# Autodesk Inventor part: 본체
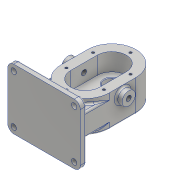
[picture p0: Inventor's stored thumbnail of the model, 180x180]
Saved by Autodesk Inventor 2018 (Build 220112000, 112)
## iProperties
Created: 2020-09
Part Number: 본체
Material: 알루미늄 6061
Document SubType Name: Modeling
Designer: Administrator
Density: 2.7 g/cm^3
Appearance: 알루미늄 - 평지
Mass: 1440.46 g
Surface Area: 785.636 cm^2
Volume: 533.505 cm^3
Author: Administrator
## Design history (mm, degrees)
sketch "스케치2"
  geometry: L1 (0, -22)-(0, 22); L2 (40, -22)-(40, 22); L3 (-40, 22)-(-40, -22); A1 r 40 centre (0, -22) between (-40, -22) and (40, -22); A2 r 40 centre (0, 22) between (40, 22) and (-40, 22); 1 further point
  constraints: 8 end point, 4 point on circle, 4 tangent, 2 centre point, 1 midpoint, 1 parallel, 1 vertical
  dimensions: "d8" = 40 radius of A2; "d9" = 44 distance of L2.start L2.end
extrude "돌출1" new body sketch "스케치2" distance "d11" = 53; taper "d12" = 0 deg
sketch "스케치3"
  geometry: C1 r 19 at (0, 22); A1 r 40 centre (0, 22) between (40, 22) and (-40, 22) reference; 1 further point
  constraints: 1 centre point, 1 coincident
  dimensions: "d13" = 38 diameter of C1
extrude "돌출2" join sketch "스케치3" distance "d14" = 17; taper "d15" = 0 deg
node "작업 평면1"
sketch "스케치4"
  geometry: L1 (40, 53)-(-40, 53) reference; L2 (-60, 83)-(-60, -17); L3 (60, 83)-(60, -17); L4 (-19, -17)-(19, -17) reference; L5 (0, -17)-(0, 83); L6 (60, -17)-(-60, -17); L7 (60, 83)-(-60, 83); 1 further point
  constraints: 10 end point, 2 parallel, 1 horizontal, 1 midpoint, 1 perpendicular, 1 vertical
  dimensions: "d19" = 100 distance of L5.start L5.end; "d89" = 120 distance of L3.end L2.end; "d90" = 30 distance between parallel lines of L1 L7; "d91" = 70 distance between parallel lines of L1 L6; "d92" = 60 distance between parallel lines of L3 L5
extrude "돌출3" join sketch "스케치4" distance "d20" = 10; taper "d21" = 0 deg
sketch "스케치5"
  geometry: L1 (60, 17)-(-60, 17) reference; L2 (0, -8)-(0, -45); L3 (40, -45)-(40, -8); L4 (-40, -45)-(-40, -8); L5 (-40, -45)-(40, -45); L6 (-40, -8)-(40, -8); 1 further point
  constraints: 10 end point, 2 horizontal, 1 vertical
  dimensions: "d23" = 37 distance of L2.start L2.end; "d26" = 40 distance between parallel lines of L2 L3; "d27" = 40 distance between parallel lines of L2 L4; "d93" = 25 distance between parallel lines of L1 L6; "d94" = 62 distance between parallel lines of L1 L5; "d95" = 20 distance from line of L1.start L3; "d96" = 25 distance from line of L2.start L1
extrude "돌출4" join sketch "스케치5" stored distance "d28" = 10; taper "d29" = 0 deg
sketch "스케치6"
  geometry: L1 (22, 53)-(-22, 53) reference; L2 (0, 53)-(0, 39); C1 r 11 at (0, 39); 1 further point
  constraints: 2 end point, 1 centre point, 1 coincident, 1 midpoint, 1 vertical
  dimensions: "d30" = 14 distance of L2.start L2.end; "d31" = 22 diameter of C1
extrude "돌출5" join sketch "스케치6" stored distance "d32" = 100; taper "d33" = 0 deg
sketch "스케치7"
  geometry: L1 (-24, 22)-(-24, -22); L2 (24, 22)-(24, -22); A1 r 40 centre (0, 22) between (40, 22) and (-40, 22) reference; A2 r 24 centre (0, 22) between (24, 22) and (-24, 22); A3 r 40 centre (0, -22) between (-40, -22) and (40, -22) reference; A4 r 24 centre (0, -22) between (-24, -22) and (24, -22); 1 further point
  constraints: 4 end point, 4 point on circle, 2 centre point, 2 coincident, 2 tangent, 2 vertical
  dimensions: "d34" = 48 diameter of A2; "d35" = 48 diameter of A4
extrude "돌출6" cut sketch "스케치7" distance "d36" = 29; taper "d37" = 0 deg
sketch "스케치8"
  geometry: C1 r 12.5 at (0, 22); C2 r 12.5 at (0, -22); A1 r 24 centre (0, 22) between (24, 22) and (-24, 22) reference; A2 r 24 centre (0, -22) between (-24, -22) and (24, -22) reference; 1 further point
  constraints: 2 centre point, 2 coincident
  dimensions: "d38" = 25 diameter of C1; "d39" = 25 diameter of C2
extrude "돌출7" cut sketch "스케치8" distance "d40" = 15; taper "d41" = 0 deg
sketch "스케치9"
  geometry: C1 r 12.5 at (0, 0) reference; C2 r 8.5 at (0, 0); 1 further point
  constraints: 1 centre point, 1 coincident
  dimensions: "d42" = 17 diameter of C2
extrude "돌출8" cut sketch "스케치9" extent not by distance; stored distance "d43" = 15; taper "d44" = 0 deg
sketch "스케치10"
  geometry: C1 r 19 at (0, 0) reference; C2 r 14 at (0, 0); 1 further point
  constraints: 1 centre point, 1 coincident
  dimensions: "d45" = 28 diameter of C2
extrude "돌출9" cut sketch "스케치10" distance "d46" = 7.3; taper "d47" = 0 deg
fillet "모깎기1" dims "d48" = 0.5
chamfer "모따기1" distance "d49" = 0.7; stored, may be unused: second distance "d50" = 2, angle "d51" = 30 deg
sketch "스케치11"
  geometry: C1 r 12.5 at (0, 22) reference; 8 further points
  dimensions: "d97" = 31 distance of C1.centre point (31, 22); "d98" = 38.01316 distance of point (0, 0) point (31, 22); "d99" = 53.82379 distance of C1.centre point (31, -22); "d100" = 38.01316 distance of point (0, 0) point (31, -22); "d101" = 31 distance of C1.centre point (0, 53); "d102" = 53 distance of point (0, 0) point (0, 53); "d103" = 75 distance of C1.centre point (0, -53); "d104" = 31 distance of C1.centre point (-31, 22); "d105" = 53.82379 distance of C1.centre point (-31, -22); "d106" = 53 distance of point (0, 0) point (0, -53); "d107" = 38.01316 distance of point (0, 0) point (-31, 22); "d108" = 38.01316 distance of point (0, 0) point (-31, -22)
hole "구멍1" sketch "스케치11" at (-31, 22), (31, 22), (0, 53), (0, -53), (31, -22), (-31, -22) diameter "d54" = 4.134; stored, may be unused: countersink angle "d58" = 90 deg, drill point angle "d60" = 118 deg; dims "d55" = 10, "d56" = 4, "d57" = 2, "d59" = 12
sketch "스케치12"
  geometry: C1 r 11 at (0, 0) reference; 2 further points
  constraints: 1 coincident
hole "구멍2" sketch "스케치12" at (0, 0) diameter "d61" = 8.376; stored, may be unused: countersink angle "d65" = 90 deg, drill point angle "d67" = 118 deg; dims "d62" = 20, "d63" = 4, "d64" = 2, "d66" = 27.3
fillet "모깎기2" dims "d68" = 10
fillet "모깎기3" dims "d69" = 3
sketch "스케치13"
  geometry: C1 r 4.5 at (-50, 7); C2 r 4.5 at (-50, -73); C3 r 4.5 at (50, -73); C4 r 4.5 at (50, 7); A1 r 10 centre (-50, 7) between (-50, 17) and (-60, 7) reference; A2 r 10 centre (-50, -73) between (-60, -73) and (-50, -83) reference; A3 r 10 centre (50, -73) between (50, -83) and (60, -73) reference; A4 r 10 centre (50, 7) between (60, 7) and (50, 17) reference; 1 further point
  constraints: 4 centre point, 4 coincident
  dimensions: "d70" = 9 diameter of C1; "d71" = 9 diameter of C2; "d72" = 9 diameter of C3; "d73" = 9 diameter of C4
extrude "돌출10" cut sketch "스케치13" extent not by distance; stored distance "d74" = 7.3; taper "d75" = 0 deg
chamfer "모따기2" distance "d76" = 1; stored, may be unused: second distance "d77" = 2, angle "d78" = 45 deg
chamfer "모따기3" distance "d79" = 1; stored, may be unused: second distance "d80" = 2, angle "d81" = 45 deg
fillet "모깎기4" dims "d82" = 3
sketch "스케치14"
  geometry: L1 (-50, -83)-(50, -83) reference; L2 (-60, 7)-(-60, -73) reference; 2 further points
  constraints: 1 other
  dimensions: "d84" = 12 distance from line of L1 point (0, -71); "d85" = 60 distance from line of L2 point (0, -71)
feature "엠보싱1" sketch "스케치14" dims "d86" = 0.5, "d87" = 0
node "솔리드1"
